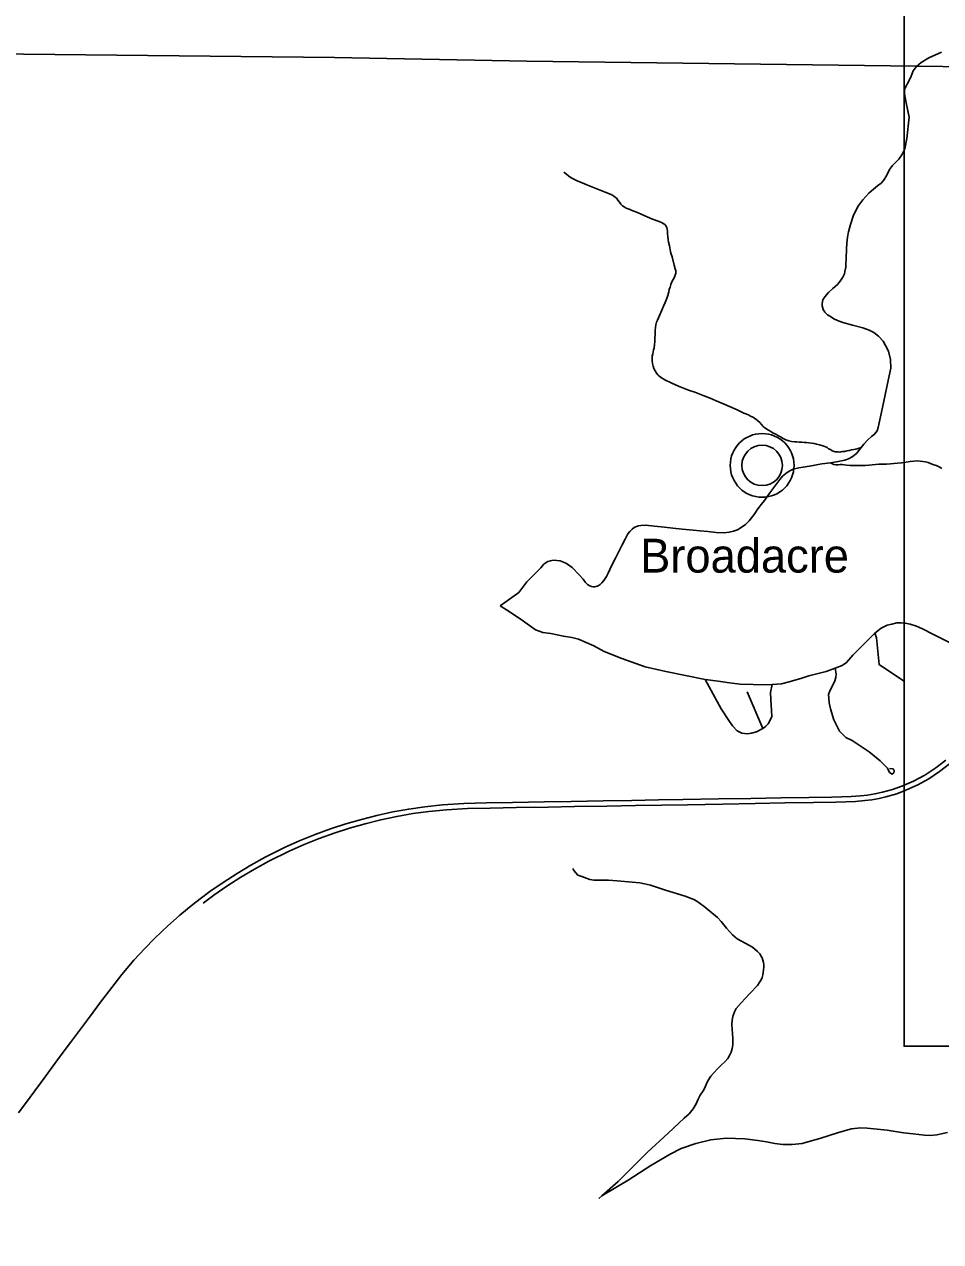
# Model space of a CAD drawing. Extents: x 2402298 to 2498138, y 789485 to 950881.
# Drawn here: x 2437350 to 2448638, y 856862 to 871864 of the extents above; entities that cross this region are included whole.
import ezdxf

# ---------------------------------------------------------------- set-up
doc = ezdxf.new("R2010")
doc.units = 0
for name, color, linetype in [('GM_X_County_Road', 7, 'Continuous'), ('GM_X_State_Route', 7, 'Continuous'), ('GM_X_Township', 7, 'Continuous'), ('GM_X_Township_Road', 7, 'Continuous'), ('GM_X_Unincorporated', 7, 'Continuous'), ('GM_X_Unincorporated_Text', 7, 'Continuous'), ('GM_X_US_Route', 7, 'Continuous'), ('SH_Text', 7, 'Continuous')]:
    doc.layers.add(name, color=color, linetype=linetype)

msp = doc.modelspace()

# ---------------------------------------------------------------- linework, layer by layer
at = {"layer": 'GM_X_County_Road'}
for points in [[(2443210, 864697), (2443288, 864647), (2443469, 864530), (2443648, 864404), (2443737, 864371), (2443836, 864356), (2443991, 864323), (2444093, 864308), (2444176, 864286), (2444364, 864205), (2444493, 864135), (2444710, 864048), (2444998, 863945), (2445252, 863890), (2445494, 863840), (2445739, 863791), (2445896, 863768), (2446036, 863749), (2446167, 863733), (2446329, 863727), (2446477, 863724), (2446561, 863729), (2446679, 863738), (2446755, 863758), (2446914, 863803), (2447016, 863834), (2447227, 863891), (2447338, 863931), (2447423, 863962), (2447479, 863999), (2447556, 864091), (2447709, 864242), (2447829, 864363), (2447907, 864422), (2447978, 864458), (2448037, 864474), (2448098, 864487), (2448151, 864488), (2448202, 864486), (2448264, 864473), (2448340, 864448), (2448415, 864413), (2448552, 864344)], [(2448552, 864344), (2448641, 864299), (2448876, 864182), (2449005, 864111), (2449066, 864071), (2449119, 864030), (2449219, 863942), (2449346, 863825), (2449440, 863736), (2449509, 863672), (2449531, 863651)]]:
    msp.add_lwpolyline(points, dxfattribs=at)
at = {"layer": 'GM_X_State_Route'}
for points in [[(2447659, 866650), (2447691, 866690), (2447741, 866744), (2447787, 866784), (2447825, 866813), (2447855, 866854), (2447870, 866897), (2447922, 867141), (2447992, 867475), (2448025, 867629), (2448019, 867732), (2447996, 867835), (2447960, 867906), (2447929, 867961), (2447874, 868022), (2447816, 868065), (2447759, 868094), (2447679, 868124), (2447551, 868159), (2447434, 868189), (2447366, 868214), (2447322, 868237), (2447280, 868263), (2447246, 868283), (2447211, 868316), (2447190, 868351), (2447178, 868396), (2447178, 868426), (2447187, 868471), (2447210, 868508), (2447255, 868558), (2447312, 868609), (2447368, 868660), (2447402, 868701), (2447434, 868748), (2447454, 868791), (2447459, 868820), (2447472, 868873), (2447472, 868910), (2447474, 868976), (2447478, 869096), (2447481, 869168), (2447490, 869240), (2447503, 869308), (2447528, 869397), (2447562, 869502), (2447618, 869619), (2447680, 869702), (2447752, 869783), (2447811, 869834), (2447862, 869873), (2447905, 869909), (2447936, 869942), (2447971, 869996), (2448009, 870077), (2448044, 870125), (2448123, 870205), (2448162, 870256), (2448195, 870329), (2448223, 870458), (2448250, 870720), (2448213, 870898), (2448192, 871008), (2448192, 871061), (2448212, 871107), (2448244, 871156), (2448277, 871227), (2448301, 871291), (2448341, 871346), (2448397, 871394), (2448492, 871450), (2448647, 871520)], [(2447281, 866462), (2447356, 866473), (2447458, 866493), (2447505, 866511), (2447549, 866535), (2447601, 866577), (2447659, 866650)], [(2446350, 865837), (2446388, 865892), (2446431, 865953), (2446469, 865998), (2446535, 866089), (2446658, 866254), (2446691, 866295), (2446730, 866329), (2446774, 866357), (2446821, 866381), (2446893, 866400), (2447048, 866425), (2447129, 866438)], [(2447129, 866438), (2447176, 866447), (2447281, 866462)], [(2443210, 864697), (2443442, 864863), (2443541, 864996), (2443648, 865099), (2443713, 865166), (2443745, 865206), (2443765, 865224), (2443798, 865244), (2443830, 865254), (2443866, 865260), (2443908, 865258), (2443951, 865251), (2443992, 865237), (2444029, 865219), (2444100, 865170), (2444185, 865081), (2444234, 865025), (2444262, 864986), (2444286, 864962), (2444316, 864946), (2444337, 864937), (2444358, 864932), (2444377, 864932), (2444395, 864936), (2444419, 864945), (2444444, 864961), (2444465, 864983), (2444488, 865010), (2444521, 865061), (2444541, 865102), (2444585, 865192), (2444631, 865285), (2444671, 865358), (2444716, 865452), (2444751, 865520), (2444784, 865585), (2444808, 865616), (2444838, 865645), (2444861, 865663), (2444890, 865677), (2444917, 865685), (2444946, 865690), (2445001, 865691), (2445115, 865678), (2445235, 865666), (2445340, 865657), (2445455, 865642), (2445588, 865629), (2445677, 865622), (2445772, 865613), (2445872, 865602), (2445970, 865599), (2446034, 865605), (2446086, 865617), (2446137, 865636), (2446195, 865670), (2446233, 865700), (2446279, 865744), (2446341, 865825), (2446350, 865837)]]:
    msp.add_lwpolyline(points, dxfattribs=at)
at = {"layer": 'GM_X_Township'}
msp.add_lwpolyline([(2436952, 871501), (2441170, 871455), (2443539, 871409), (2448340, 871349), (2451564, 871308), (2453075, 871274), (2455047, 871253), (2454976, 868366), (2454948, 867221), (2454912, 865985), (2454911, 865959), (2454910, 865921), (2454853, 863679), (2454854, 862987), (2454763, 859062), (2454590, 849912), (2454510, 846829), (2454470, 845007), (2454435, 843954)], dxfattribs=at)
at = {"layer": 'GM_X_Township_Road'}
msp.add_line((2446446, 863185), (2446256, 863639), dxfattribs=at)
for points in [[(2447348, 866597), (2447338, 866598), (2447328, 866601), (2447302, 866610), (2447281, 866623), (2447257, 866635), (2447239, 866649), (2447221, 866658), (2447200, 866666), (2447176, 866674), (2447145, 866683), (2447110, 866691), (2447081, 866698), (2447048, 866703), (2447015, 866706), (2446987, 866710), (2446958, 866713), (2446930, 866714), (2446895, 866717), (2446865, 866720), (2446837, 866720), (2446801, 866724), (2446768, 866732), (2446732, 866746), (2446700, 866760), (2446667, 866781), (2446632, 866798), (2446607, 866814), (2446576, 866828), (2446545, 866848), (2446516, 866862), (2446474, 866891), (2446451, 866909), (2446433, 866931), (2446410, 866956), (2446387, 866978), (2446359, 867001), (2446323, 867025), (2446297, 867037), (2446270, 867051), (2446213, 867074), (2446132, 867114), (2446037, 867155), (2445972, 867183), (2445873, 867225), (2445798, 867257), (2445714, 867291), (2445608, 867330), (2445532, 867355), (2445410, 867405), (2445328, 867442), (2445239, 867483), (2445185, 867515), (2445158, 867541), (2445136, 867566), (2445120, 867593), (2445106, 867623), (2445096, 867653), (2445089, 867684), (2445085, 867716), (2445084, 867749), (2445086, 867776), (2445092, 867805), (2445101, 867852), (2445108, 867874), (2445114, 867917), (2445118, 867952), (2445119, 867995), (2445121, 868044), (2445123, 868095), (2445126, 868128), (2445129, 868163), (2445139, 868195), (2445152, 868219), (2445175, 868275), (2445202, 868340), (2445223, 868390), (2445244, 868437), (2445262, 868477), (2445278, 868524), (2445291, 868570), (2445295, 868597), (2445304, 868627), (2445316, 868657), (2445324, 868683), (2445343, 868718), (2445359, 868747), (2445368, 868774), (2445375, 868800), (2445374, 868826), (2445369, 868851), (2445356, 868896), (2445329, 868999), (2445316, 869043), (2445308, 869085), (2445296, 869134), (2445285, 869182), (2445281, 869213), (2445277, 869251), (2445275, 869283), (2445273, 869317), (2445269, 869341), (2445267, 869357), (2445258, 869379), (2445246, 869392), (2445229, 869406), (2445208, 869417), (2445170, 869434), (2445089, 869465), (2444958, 869523), (2444902, 869545), (2444846, 869567), (2444801, 869586), (2444762, 869600), (2444738, 869614), (2444720, 869629), (2444700, 869650), (2444680, 869675), (2444662, 869698), (2444649, 869719), (2444629, 869736), (2444614, 869746), (2444586, 869762), (2444560, 869776), (2444506, 869798), (2444278, 869888), (2444220, 869910), (2444167, 869933), (2444121, 869958), (2444085, 869974), (2444058, 869995), (2444028, 870020), (2443997, 870043)], [(2447281, 866462), (2447356, 866473), (2447458, 866493), (2447505, 866511), (2447549, 866535), (2447601, 866577), (2447659, 866650)], [(2447659, 866650), (2447624, 866636), (2447593, 866631), (2447569, 866626), (2447539, 866620), (2447513, 866614), (2447484, 866608), (2447454, 866601), (2447425, 866600), (2447410, 866596), (2447398, 866594), (2447376, 866595), (2447353, 866596), (2447348, 866597)], [(2448652, 866390), (2448621, 866411), (2448582, 866426), (2448544, 866442), (2448513, 866453), (2448483, 866463), (2448453, 866472), (2448418, 866479), (2448387, 866483), (2448352, 866485), (2448261, 866477), (2448162, 866462), (2448108, 866455), (2448063, 866451), (2448019, 866449), (2447973, 866446), (2447875, 866443), (2447711, 866429), (2447645, 866426), (2447598, 866427), (2447561, 866426), (2447522, 866429), (2447483, 866432), (2447451, 866435), (2447427, 866438), (2447402, 866439), (2447375, 866436), (2447345, 866435), (2447321, 866439), (2447305, 866448), (2447281, 866462)], [(2447829, 864363), (2447848, 864303), (2447880, 863974), (2448192, 863767)], [(2448010, 862694), (2448053, 862689), (2448065, 862663), (2448060, 862642), (2448039, 862624), (2448008, 862645), (2447985, 862697), (2447893, 862787), (2447759, 862897), (2447547, 863038), (2447472, 863074), (2447392, 863152), (2447321, 863294), (2447281, 863427), (2447265, 863501), (2447259, 863560), (2447258, 863606), (2447267, 863639), (2447288, 863684), (2447330, 863760), (2447348, 863816), (2447351, 863858), (2447338, 863931)], [(2445739, 863791), (2445935, 863427), (2446030, 863285), (2446075, 863218), (2446130, 863156), (2446189, 863127), (2446259, 863120), (2446309, 863127), (2446368, 863146), (2446446, 863185), (2446482, 863212), (2446513, 863246), (2446534, 863279), (2446557, 863335), (2446556, 863410), (2446545, 863542), (2446542, 863629), (2446561, 863729)], [(2446438, 860360), (2446433, 860374), (2446411, 860409), (2446381, 860439), (2446321, 860490), (2446284, 860513), (2446130, 860595), (2446076, 860642), (2446001, 860724), (2445936, 860808), (2445888, 860857), (2445723, 860994), (2445635, 861057), (2445596, 861080), (2445490, 861119), (2445248, 861193), (2445063, 861254), (2444989, 861273), (2444931, 861284), (2444836, 861291), (2444654, 861311), (2444547, 861316), (2444461, 861316), (2444367, 861318), (2444316, 861326), (2444218, 861364), (2444169, 861377), (2444119, 861437), (2444108, 861461)], [(2444428, 857395), (2444466, 857428), (2444666, 857602), (2445024, 857960), (2445282, 858201), (2445480, 858384), (2445540, 858438), (2445589, 858499), (2445625, 858559), (2445651, 858618), (2445677, 858667), (2445712, 858723), (2445734, 858760), (2445759, 858821), (2445779, 858855), (2445808, 858901), (2445838, 858937), (2445894, 858996), (2445930, 859034), (2445984, 859081), (2446017, 859120), (2446038, 859157), (2446058, 859198), (2446069, 859241), (2446078, 859289), (2446078, 859367), (2446067, 859539), (2446071, 859592), (2446079, 859637), (2446097, 859696), (2446120, 859737), (2446180, 859807), (2446288, 859922), (2446381, 860020), (2446404, 860054), (2446427, 860091), (2446438, 860119), (2446448, 860150), (2446453, 860181), (2446457, 860209), (2446461, 860248), (2446460, 860276), (2446455, 860304), (2446448, 860333), (2446438, 860360)], [(2444466, 857428), (2444788, 857622), (2445066, 857799), (2445304, 857941), (2445440, 858011), (2445621, 858074), (2445805, 858119), (2445994, 858136), (2446225, 858131), (2446387, 858110), (2446494, 858091), (2446594, 858073), (2446694, 858059), (2446811, 858059), (2446931, 858073), (2447031, 858101), (2447148, 858135), (2447381, 858208), (2447539, 858251), (2447650, 858264)], [(2447650, 858264), (2447732, 858260), (2447978, 858236), (2448179, 858205), (2448300, 858190), (2448441, 858175), (2448512, 858171), (2448592, 858180), (2448724, 858208)]]:
    msp.add_lwpolyline(points, dxfattribs=at)
at = {"layer": 'GM_X_Unincorporated'}
for radius in [393, 249]:
    msp.add_circle((2446439, 866429), radius, dxfattribs=at)
at = {"layer": 'GM_X_US_Route'}
for points in [[(2437276, 858450), (2437420, 858642), (2437606, 858895), (2437726, 859057), (2437793, 859147), (2437918, 859316), (2438129, 859598), (2438199, 859692), (2438290, 859815), (2438427, 859996), (2438550, 860153), (2438700, 860330), (2438834, 860475), (2438949, 860593), (2439043, 860685), (2439115, 860751), (2439266, 860886), (2439358, 860962), (2439445, 861032), (2439636, 861177), (2439798, 861289), (2439970, 861399), (2440139, 861501), (2440316, 861599), (2440565, 861723), (2440748, 861805), (2440934, 861880), (2441122, 861949), (2441311, 862012), (2441504, 862067), (2441694, 862115), (2441891, 862159), (2442085, 862194), (2442285, 862222), (2442503, 862245), (2442765, 862263), (2443042, 862269), (2443362, 862275), (2443758, 862281), (2444085, 862287), (2444481, 862293), (2444833, 862300), (2445164, 862306), (2445464, 862311), (2445903, 862318), (2446298, 862325), (2446670, 862331), (2447016, 862337), (2447298, 862341), (2447419, 862344), (2447537, 862348), (2447650, 862356), (2447736, 862366), (2447829, 862381), (2447920, 862400), (2448044, 862434), (2448161, 862475), (2448305, 862537), (2448444, 862613), (2448580, 862701), (2448703, 862797)], [(2439553, 861033), (2439683, 861131), (2439846, 861245), (2440015, 861354), (2440187, 861454), (2440361, 861551), (2440611, 861674), (2440795, 861755), (2440980, 861830), (2441168, 861898), (2441357, 861959), (2441550, 862013), (2441740, 862061), (2441938, 862102), (2442134, 862137), (2442331, 862164), (2442549, 862186), (2442810, 862201), (2443087, 862206), (2443408, 862212), (2443804, 862219), (2444126, 862224), (2444524, 862230), (2444878, 862237), (2445203, 862242), (2445520, 862247), (2445956, 862255), (2446352, 862262), (2446717, 862269), (2447072, 862274), (2447349, 862279), (2447471, 862282), (2447589, 862287), (2447704, 862298), (2447789, 862309), (2447881, 862325), (2447962, 862344), (2448097, 862383), (2448210, 862426), (2448356, 862491), (2448491, 862566), (2448626, 862655), (2448749, 862752)]]:
    msp.add_lwpolyline(points, dxfattribs=at)
at = {"layer": 'SH_Text'}
msp.add_lwpolyline([(2448187, 889729), (2496836, 889729), (2496836, 859271), (2448187, 859271)], close=True, dxfattribs=at)

# ---------------------------------------------------------------- texts
at = {"layer": 'GM_X_Unincorporated_Text'}
msp.add_text('Broadacre', height=417, rotation=0, dxfattribs=at).set_placement((2444936, 865108))

doc.saveas('drawing.dxf')
